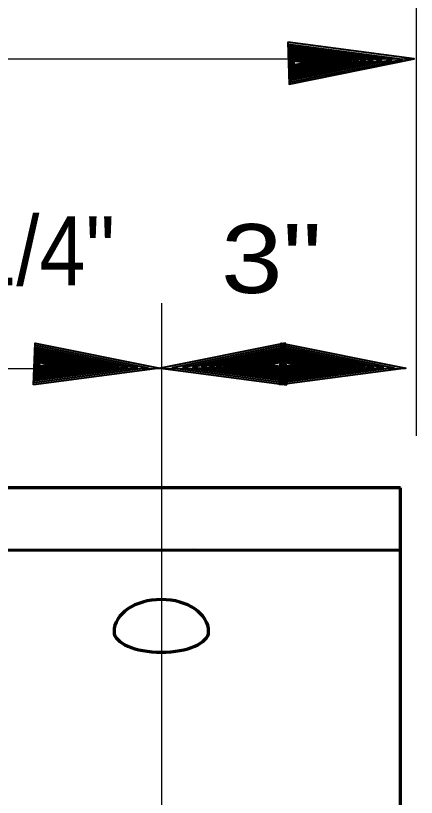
# Model space of a CAD drawing. Extents: x 895.6 to 930.4, y -2278.6 to -2254.7.
# Drawn here: x 918.427 to 919.174, y -2271.618 to -2270.16 of the extents above; entities that cross this region are included whole.
import ezdxf

# ---------------------------------------------------------------- set-up
doc = ezdxf.new("R2010")
doc.units = 0
doc.header["$LTSCALE"] = 0.051
doc.layers.add('1', color=7, linetype='Continuous', lineweight=70)
doc.layers.add('3', color=7, linetype='Continuous', lineweight=40)

msp = doc.modelspace()

# ---------------------------------------------------------------- hatches: boundary and pattern name
at = {"layer": '3'}
for points in [[(918.93467, -2270.20958), (918.93733, -2270.28758), (919.16992, -2270.24067), (919.16992, -2270.24067)], [(918.93583, -2270.2135), (918.93825, -2270.28367), (919.14758, -2270.2415), (919.14758, -2270.2415)], [(918.93692, -2270.217), (918.93908, -2270.28017), (919.1275, -2270.24208), (919.1275, -2270.24208)], [(918.93783, -2270.22008), (918.93983, -2270.27683), (919.10942, -2270.24267), (919.10942, -2270.24267)], [(918.93867, -2270.22275), (918.94042, -2270.274), (919.09317, -2270.24317), (919.09317, -2270.24317)], [(918.93958, -2270.2255), (918.94108, -2270.27142), (919.0785, -2270.24375), (919.0785, -2270.24375)], [(918.94025, -2270.22775), (918.94158, -2270.26917), (919.06533, -2270.24417), (919.06533, -2270.24417)], [(918.941, -2270.22967), (918.94208, -2270.267), (919.05333, -2270.2445), (919.05333, -2270.2445)], [(918.94133, -2270.23158), (918.94258, -2270.26525), (919.04275, -2270.24508), (919.04275, -2270.24508)], [(918.942, -2270.23325), (918.94308, -2270.26358), (919.033, -2270.24525), (919.033, -2270.24525)], [(918.9425, -2270.23475), (918.94333, -2270.26192), (919.02433, -2270.24558), (919.02433, -2270.24558)], [(918.94283, -2270.23617), (918.94375, -2270.26058), (919.01667, -2270.24592), (919.01667, -2270.24592)], [(918.94325, -2270.23725), (918.944, -2270.25933), (919.0095, -2270.24608), (919.0095, -2270.24608)], [(918.94375, -2270.23842), (918.94417, -2270.25825), (919.00333, -2270.24633), (919.00333, -2270.24633)], [(918.94392, -2270.23933), (918.94458, -2270.25725), (918.99767, -2270.24642), (918.99767, -2270.24642)], [(918.94425, -2270.24033), (918.94467, -2270.25642), (918.99258, -2270.24675), (918.99258, -2270.24675)], [(918.9445, -2270.24108), (918.94492, -2270.25567), (918.988, -2270.24692), (918.988, -2270.24692)], [(918.94458, -2270.24183), (918.94508, -2270.25483), (918.98383, -2270.24708), (918.98383, -2270.24708)], [(918.94492, -2270.24225), (918.94525, -2270.25408), (918.98025, -2270.24708), (918.98025, -2270.24708)], [(918.94517, -2270.24283), (918.9455, -2270.25342), (918.977, -2270.24708), (918.977, -2270.24708)], [(918.94542, -2270.24317), (918.94575, -2270.25275), (918.974, -2270.247), (918.974, -2270.247)], [(918.94542, -2270.24375), (918.94575, -2270.25225), (918.97117, -2270.24708), (918.97117, -2270.24708)], [(918.94558, -2270.24425), (918.94592, -2270.25183), (918.96883, -2270.24733), (918.96883, -2270.24733)], [(918.94575, -2270.2445), (918.94592, -2270.25133), (918.96658, -2270.24725), (918.96658, -2270.24725)], [(918.46067, -2270.84892), (918.46333, -2270.77092), (918.696, -2270.81783), (918.696, -2270.81783)], [(918.46192, -2270.845), (918.46425, -2270.77483), (918.67358, -2270.817), (918.67358, -2270.817)], [(918.46292, -2270.8415), (918.46508, -2270.77842), (918.6535, -2270.81642), (918.6535, -2270.81642)], [(918.9325, -2270.84892), (918.92983, -2270.77092), (918.69717, -2270.81783), (918.69717, -2270.81783)], [(918.93125, -2270.845), (918.92892, -2270.77483), (918.71958, -2270.817), (918.71958, -2270.817)], [(918.93025, -2270.8415), (918.92808, -2270.77842), (918.73967, -2270.81642), (918.73967, -2270.81642)], [(918.91925, -2270.849), (918.92192, -2270.771), (919.1545, -2270.81792), (919.1545, -2270.81792)], [(918.92042, -2270.84508), (918.92283, -2270.77492), (919.13217, -2270.81708), (919.13217, -2270.81708)], [(918.9215, -2270.84158), (918.92367, -2270.77842), (919.11208, -2270.8165), (919.11208, -2270.8165)], [(918.46392, -2270.83842), (918.46583, -2270.78167), (918.63542, -2270.81583), (918.63542, -2270.81583)], [(918.46467, -2270.83575), (918.4665, -2270.78458), (918.61917, -2270.81533), (918.61917, -2270.81533)], [(918.46567, -2270.83308), (918.46717, -2270.78708), (918.6045, -2270.81483), (918.6045, -2270.81483)], [(918.46625, -2270.83075), (918.46758, -2270.78933), (918.59133, -2270.81433), (918.59133, -2270.81433)], [(918.467, -2270.82883), (918.46808, -2270.7915), (918.57933, -2270.814), (918.57933, -2270.814)], [(918.92925, -2270.83842), (918.92733, -2270.78167), (918.75775, -2270.81583), (918.75775, -2270.81583)], [(918.9285, -2270.83575), (918.92667, -2270.78458), (918.774, -2270.81533), (918.774, -2270.81533)], [(918.9275, -2270.83308), (918.926, -2270.78708), (918.78867, -2270.81483), (918.78867, -2270.81483)], [(918.92692, -2270.83075), (918.92558, -2270.78933), (918.80183, -2270.81433), (918.80183, -2270.81433)], [(918.92617, -2270.82883), (918.92508, -2270.7915), (918.81383, -2270.814), (918.81383, -2270.814)], [(918.92242, -2270.8385), (918.92442, -2270.78175), (919.094, -2270.81592), (919.094, -2270.81592)], [(918.92325, -2270.83583), (918.925, -2270.78458), (919.07775, -2270.81542), (919.07775, -2270.81542)], [(918.92417, -2270.83308), (918.92567, -2270.78717), (919.06308, -2270.81483), (919.06308, -2270.81483)], [(918.92483, -2270.83083), (918.92617, -2270.78942), (919.04992, -2270.81442), (919.04992, -2270.81442)], [(918.92558, -2270.82892), (918.92667, -2270.79158), (919.03792, -2270.81408), (919.03792, -2270.81408)], [(918.46733, -2270.827), (918.46867, -2270.79333), (918.56875, -2270.8135), (918.56875, -2270.8135)], [(918.468, -2270.82525), (918.46908, -2270.79492), (918.55908, -2270.81325), (918.55908, -2270.81325)], [(918.4685, -2270.82375), (918.46942, -2270.79658), (918.55042, -2270.81292), (918.55042, -2270.81292)], [(918.46883, -2270.82233), (918.46975, -2270.798), (918.54267, -2270.81258), (918.54267, -2270.81258)], [(918.46933, -2270.82125), (918.47, -2270.79917), (918.5355, -2270.81242), (918.5355, -2270.81242)], [(918.46975, -2270.82008), (918.47025, -2270.80025), (918.52942, -2270.81225), (918.52942, -2270.81225)], [(918.47, -2270.81917), (918.47058, -2270.80125), (918.52367, -2270.81208), (918.52367, -2270.81208)], [(918.47025, -2270.81825), (918.47067, -2270.80208), (918.51858, -2270.81175), (918.51858, -2270.81175)], [(918.4705, -2270.81742), (918.471, -2270.80283), (918.514, -2270.81158), (918.514, -2270.81158)], [(918.47067, -2270.81667), (918.47108, -2270.80367), (918.50992, -2270.8115), (918.50992, -2270.8115)], [(918.471, -2270.81625), (918.47125, -2270.80442), (918.50625, -2270.8115), (918.50625, -2270.8115)], [(918.47117, -2270.81567), (918.4715, -2270.80508), (918.503, -2270.81142), (918.503, -2270.81142)], [(918.47142, -2270.81533), (918.47175, -2270.80575), (918.5, -2270.81158), (918.5, -2270.81158)], [(918.47142, -2270.81475), (918.47175, -2270.80625), (918.49725, -2270.81142), (918.49725, -2270.81142)], [(918.47158, -2270.81425), (918.47192, -2270.80667), (918.49483, -2270.81117), (918.49483, -2270.81117)], [(918.47175, -2270.814), (918.472, -2270.80717), (918.49267, -2270.81125), (918.49267, -2270.81125)], [(918.92583, -2270.827), (918.9245, -2270.79333), (918.82442, -2270.8135), (918.82442, -2270.8135)], [(918.92517, -2270.82525), (918.92408, -2270.79492), (918.83408, -2270.81325), (918.83408, -2270.81325)], [(918.92467, -2270.82375), (918.92375, -2270.79658), (918.84275, -2270.81292), (918.84275, -2270.81292)], [(918.92433, -2270.82233), (918.92342, -2270.798), (918.8505, -2270.81258), (918.8505, -2270.81258)], [(918.92383, -2270.82125), (918.92317, -2270.79917), (918.85767, -2270.81242), (918.85767, -2270.81242)], [(918.92342, -2270.82008), (918.92292, -2270.80025), (918.86375, -2270.81225), (918.86375, -2270.81225)], [(918.92317, -2270.81917), (918.92258, -2270.80125), (918.8695, -2270.81208), (918.8695, -2270.81208)], [(918.92292, -2270.81825), (918.9225, -2270.80208), (918.87458, -2270.81175), (918.87458, -2270.81175)], [(918.92267, -2270.81742), (918.92217, -2270.80283), (918.87917, -2270.81158), (918.87917, -2270.81158)], [(918.9225, -2270.81667), (918.92208, -2270.80367), (918.88325, -2270.8115), (918.88325, -2270.8115)], [(918.92217, -2270.81625), (918.92192, -2270.80442), (918.88692, -2270.8115), (918.88692, -2270.8115)], [(918.922, -2270.81567), (918.92167, -2270.80508), (918.89017, -2270.81142), (918.89017, -2270.81142)], [(918.92175, -2270.81533), (918.92142, -2270.80575), (918.89317, -2270.81158), (918.89317, -2270.81158)], [(918.92175, -2270.81475), (918.92142, -2270.80625), (918.89592, -2270.81142), (918.89592, -2270.81142)], [(918.92158, -2270.81425), (918.92125, -2270.80667), (918.89833, -2270.81117), (918.89833, -2270.81117)], [(918.92142, -2270.814), (918.92117, -2270.80717), (918.9005, -2270.81125), (918.9005, -2270.81125)], [(918.92592, -2270.827), (918.92717, -2270.79333), (919.02733, -2270.8135), (919.02733, -2270.8135)], [(918.92658, -2270.82533), (918.92767, -2270.795), (919.01758, -2270.81333), (919.01758, -2270.81333)], [(918.92708, -2270.82383), (918.92792, -2270.79667), (919.00892, -2270.813), (919.00892, -2270.813)], [(918.92742, -2270.82242), (918.92833, -2270.798), (919.00125, -2270.81267), (919.00125, -2270.81267)], [(918.92783, -2270.82133), (918.92858, -2270.79925), (918.99408, -2270.8125), (918.99408, -2270.8125)], [(918.92833, -2270.82017), (918.92875, -2270.80033), (918.98792, -2270.81225), (918.98792, -2270.81225)], [(918.9285, -2270.81925), (918.92917, -2270.80133), (918.98225, -2270.81217), (918.98225, -2270.81217)], [(918.92883, -2270.81825), (918.92925, -2270.80217), (918.97717, -2270.81183), (918.97717, -2270.81183)], [(918.92908, -2270.8175), (918.9295, -2270.80292), (918.97258, -2270.81167), (918.97258, -2270.81167)], [(918.92917, -2270.81675), (918.92967, -2270.80375), (918.96842, -2270.8115), (918.96842, -2270.8115)], [(918.9295, -2270.81633), (918.92983, -2270.8045), (918.96483, -2270.8115), (918.96483, -2270.8115)], [(918.92975, -2270.81575), (918.93008, -2270.80517), (918.96158, -2270.8115), (918.96158, -2270.8115)], [(918.93, -2270.81542), (918.93033, -2270.80583), (918.95858, -2270.81158), (918.95858, -2270.81158)], [(918.93, -2270.81483), (918.93033, -2270.80633), (918.95575, -2270.8115), (918.95575, -2270.8115)], [(918.93017, -2270.81433), (918.9305, -2270.80675), (918.95342, -2270.81125), (918.95342, -2270.81125)], [(918.93033, -2270.81408), (918.9305, -2270.80725), (918.95117, -2270.81133), (918.95117, -2270.81133)]]:
    msp.add_hatch(color=256, dxfattribs=at).paths.add_polyline_path(points)

# ---------------------------------------------------------------- linework, layer by layer
at = {"layer": '1', "lineweight": 25}
for p, q in [((919.17408, -2270.94408), (919.17408, -2269.46433)), ((918.1585, -2270.24067), (919.16992, -2270.24067)), ((918.69942, -2273.34217), (918.69942, -2270.69617)), ((917.64958, -2270.81817), (919.1535, -2270.81817))]:
    msp.add_line(p, q, dxfattribs=at)
at = {"layer": '1'}
for p, q in [((919.14467, -2271.04083), (915.53433, -2271.04083)), ((919.14467, -2273.83717), (919.14467, -2271.04083))]:
    msp.add_line(p, q, dxfattribs=at)
msp.add_lwpolyline([(919.14442, -2271.15792), (918.759, -2271.157), (918.012, -2271.15792), (917.23617, -2271.16342), (917.23658, -2271.1625)], dxfattribs=at)
for major_axis, ratio in [((-0.08819, 0), 0.679978), ((0.08819, 0), 0.434256)]:
    msp.add_ellipse((918.69876, -2271.30925), major_axis=major_axis, ratio=ratio, start_param=3.1415927, end_param=6.2831853, dxfattribs=at)
at = {"layer": '3'}
for points in [[(918.93467, -2270.20958), (918.93733, -2270.28758), (919.16992, -2270.24067), (919.16992, -2270.24067)], [(918.93583, -2270.2135), (918.93825, -2270.28367), (919.14758, -2270.2415), (919.14758, -2270.2415)], [(918.93692, -2270.217), (918.93908, -2270.28017), (919.1275, -2270.24208), (919.1275, -2270.24208)], [(918.93783, -2270.22008), (918.93983, -2270.27683), (919.10942, -2270.24267), (919.10942, -2270.24267)], [(918.93867, -2270.22275), (918.94042, -2270.274), (919.09317, -2270.24317), (919.09317, -2270.24317)], [(918.93958, -2270.2255), (918.94108, -2270.27142), (919.0785, -2270.24375), (919.0785, -2270.24375)], [(918.94025, -2270.22775), (918.94158, -2270.26917), (919.06533, -2270.24417), (919.06533, -2270.24417)], [(918.941, -2270.22967), (918.94208, -2270.267), (919.05333, -2270.2445), (919.05333, -2270.2445)], [(918.94133, -2270.23158), (918.94258, -2270.26525), (919.04275, -2270.24508), (919.04275, -2270.24508)], [(918.942, -2270.23325), (918.94308, -2270.26358), (919.033, -2270.24525), (919.033, -2270.24525)], [(918.9425, -2270.23475), (918.94333, -2270.26192), (919.02433, -2270.24558), (919.02433, -2270.24558)], [(918.94283, -2270.23617), (918.94375, -2270.26058), (919.01667, -2270.24592), (919.01667, -2270.24592)], [(918.94325, -2270.23725), (918.944, -2270.25933), (919.0095, -2270.24608), (919.0095, -2270.24608)], [(918.94375, -2270.23842), (918.94417, -2270.25825), (919.00333, -2270.24633), (919.00333, -2270.24633)], [(918.94392, -2270.23933), (918.94458, -2270.25725), (918.99767, -2270.24642), (918.99767, -2270.24642)], [(918.94425, -2270.24033), (918.94467, -2270.25642), (918.99258, -2270.24675), (918.99258, -2270.24675)], [(918.9445, -2270.24108), (918.94492, -2270.25567), (918.988, -2270.24692), (918.988, -2270.24692)], [(918.94458, -2270.24183), (918.94508, -2270.25483), (918.98383, -2270.24708), (918.98383, -2270.24708)], [(918.94492, -2270.24225), (918.94525, -2270.25408), (918.98025, -2270.24708), (918.98025, -2270.24708)], [(918.94517, -2270.24283), (918.9455, -2270.25342), (918.977, -2270.24708), (918.977, -2270.24708)], [(918.94542, -2270.24317), (918.94575, -2270.25275), (918.974, -2270.247), (918.974, -2270.247)], [(918.94542, -2270.24375), (918.94575, -2270.25225), (918.97117, -2270.24708), (918.97117, -2270.24708)], [(918.94558, -2270.24425), (918.94592, -2270.25183), (918.96883, -2270.24733), (918.96883, -2270.24733)], [(918.94575, -2270.2445), (918.94592, -2270.25133), (918.96658, -2270.24725), (918.96658, -2270.24725)], [(918.46067, -2270.84892), (918.46333, -2270.77092), (918.696, -2270.81783), (918.696, -2270.81783)], [(918.46192, -2270.845), (918.46425, -2270.77483), (918.67358, -2270.817), (918.67358, -2270.817)], [(918.46292, -2270.8415), (918.46508, -2270.77842), (918.6535, -2270.81642), (918.6535, -2270.81642)], [(918.9325, -2270.84892), (918.92983, -2270.77092), (918.69717, -2270.81783), (918.69717, -2270.81783)], [(918.93125, -2270.845), (918.92892, -2270.77483), (918.71958, -2270.817), (918.71958, -2270.817)], [(918.93025, -2270.8415), (918.92808, -2270.77842), (918.73967, -2270.81642), (918.73967, -2270.81642)], [(918.91925, -2270.849), (918.92192, -2270.771), (919.1545, -2270.81792), (919.1545, -2270.81792)], [(918.92042, -2270.84508), (918.92283, -2270.77492), (919.13217, -2270.81708), (919.13217, -2270.81708)], [(918.9215, -2270.84158), (918.92367, -2270.77842), (919.11208, -2270.8165), (919.11208, -2270.8165)], [(918.46392, -2270.83842), (918.46583, -2270.78167), (918.63542, -2270.81583), (918.63542, -2270.81583)], [(918.46467, -2270.83575), (918.4665, -2270.78458), (918.61917, -2270.81533), (918.61917, -2270.81533)], [(918.46567, -2270.83308), (918.46717, -2270.78708), (918.6045, -2270.81483), (918.6045, -2270.81483)], [(918.46625, -2270.83075), (918.46758, -2270.78933), (918.59133, -2270.81433), (918.59133, -2270.81433)], [(918.467, -2270.82883), (918.46808, -2270.7915), (918.57933, -2270.814), (918.57933, -2270.814)], [(918.92925, -2270.83842), (918.92733, -2270.78167), (918.75775, -2270.81583), (918.75775, -2270.81583)], [(918.9285, -2270.83575), (918.92667, -2270.78458), (918.774, -2270.81533), (918.774, -2270.81533)], [(918.9275, -2270.83308), (918.926, -2270.78708), (918.78867, -2270.81483), (918.78867, -2270.81483)], [(918.92692, -2270.83075), (918.92558, -2270.78933), (918.80183, -2270.81433), (918.80183, -2270.81433)], [(918.92617, -2270.82883), (918.92508, -2270.7915), (918.81383, -2270.814), (918.81383, -2270.814)], [(918.92242, -2270.8385), (918.92442, -2270.78175), (919.094, -2270.81592), (919.094, -2270.81592)], [(918.92325, -2270.83583), (918.925, -2270.78458), (919.07775, -2270.81542), (919.07775, -2270.81542)], [(918.92417, -2270.83308), (918.92567, -2270.78717), (919.06308, -2270.81483), (919.06308, -2270.81483)], [(918.92483, -2270.83083), (918.92617, -2270.78942), (919.04992, -2270.81442), (919.04992, -2270.81442)], [(918.92558, -2270.82892), (918.92667, -2270.79158), (919.03792, -2270.81408), (919.03792, -2270.81408)], [(918.46733, -2270.827), (918.46867, -2270.79333), (918.56875, -2270.8135), (918.56875, -2270.8135)], [(918.468, -2270.82525), (918.46908, -2270.79492), (918.55908, -2270.81325), (918.55908, -2270.81325)], [(918.4685, -2270.82375), (918.46942, -2270.79658), (918.55042, -2270.81292), (918.55042, -2270.81292)], [(918.46883, -2270.82233), (918.46975, -2270.798), (918.54267, -2270.81258), (918.54267, -2270.81258)], [(918.46933, -2270.82125), (918.47, -2270.79917), (918.5355, -2270.81242), (918.5355, -2270.81242)], [(918.46975, -2270.82008), (918.47025, -2270.80025), (918.52942, -2270.81225), (918.52942, -2270.81225)], [(918.47, -2270.81917), (918.47058, -2270.80125), (918.52367, -2270.81208), (918.52367, -2270.81208)], [(918.47025, -2270.81825), (918.47067, -2270.80208), (918.51858, -2270.81175), (918.51858, -2270.81175)], [(918.4705, -2270.81742), (918.471, -2270.80283), (918.514, -2270.81158), (918.514, -2270.81158)], [(918.47067, -2270.81667), (918.47108, -2270.80367), (918.50992, -2270.8115), (918.50992, -2270.8115)], [(918.471, -2270.81625), (918.47125, -2270.80442), (918.50625, -2270.8115), (918.50625, -2270.8115)], [(918.47117, -2270.81567), (918.4715, -2270.80508), (918.503, -2270.81142), (918.503, -2270.81142)], [(918.47142, -2270.81533), (918.47175, -2270.80575), (918.5, -2270.81158), (918.5, -2270.81158)], [(918.47142, -2270.81475), (918.47175, -2270.80625), (918.49725, -2270.81142), (918.49725, -2270.81142)], [(918.47158, -2270.81425), (918.47192, -2270.80667), (918.49483, -2270.81117), (918.49483, -2270.81117)], [(918.47175, -2270.814), (918.472, -2270.80717), (918.49267, -2270.81125), (918.49267, -2270.81125)], [(918.92583, -2270.827), (918.9245, -2270.79333), (918.82442, -2270.8135), (918.82442, -2270.8135)], [(918.92517, -2270.82525), (918.92408, -2270.79492), (918.83408, -2270.81325), (918.83408, -2270.81325)], [(918.92467, -2270.82375), (918.92375, -2270.79658), (918.84275, -2270.81292), (918.84275, -2270.81292)], [(918.92433, -2270.82233), (918.92342, -2270.798), (918.8505, -2270.81258), (918.8505, -2270.81258)], [(918.92383, -2270.82125), (918.92317, -2270.79917), (918.85767, -2270.81242), (918.85767, -2270.81242)], [(918.92342, -2270.82008), (918.92292, -2270.80025), (918.86375, -2270.81225), (918.86375, -2270.81225)], [(918.92317, -2270.81917), (918.92258, -2270.80125), (918.8695, -2270.81208), (918.8695, -2270.81208)], [(918.92292, -2270.81825), (918.9225, -2270.80208), (918.87458, -2270.81175), (918.87458, -2270.81175)], [(918.92267, -2270.81742), (918.92217, -2270.80283), (918.87917, -2270.81158), (918.87917, -2270.81158)], [(918.9225, -2270.81667), (918.92208, -2270.80367), (918.88325, -2270.8115), (918.88325, -2270.8115)], [(918.92217, -2270.81625), (918.92192, -2270.80442), (918.88692, -2270.8115), (918.88692, -2270.8115)], [(918.922, -2270.81567), (918.92167, -2270.80508), (918.89017, -2270.81142), (918.89017, -2270.81142)], [(918.92175, -2270.81533), (918.92142, -2270.80575), (918.89317, -2270.81158), (918.89317, -2270.81158)], [(918.92175, -2270.81475), (918.92142, -2270.80625), (918.89592, -2270.81142), (918.89592, -2270.81142)], [(918.92158, -2270.81425), (918.92125, -2270.80667), (918.89833, -2270.81117), (918.89833, -2270.81117)], [(918.92142, -2270.814), (918.92117, -2270.80717), (918.9005, -2270.81125), (918.9005, -2270.81125)], [(918.92592, -2270.827), (918.92717, -2270.79333), (919.02733, -2270.8135), (919.02733, -2270.8135)], [(918.92658, -2270.82533), (918.92767, -2270.795), (919.01758, -2270.81333), (919.01758, -2270.81333)], [(918.92708, -2270.82383), (918.92792, -2270.79667), (919.00892, -2270.813), (919.00892, -2270.813)], [(918.92742, -2270.82242), (918.92833, -2270.798), (919.00125, -2270.81267), (919.00125, -2270.81267)], [(918.92783, -2270.82133), (918.92858, -2270.79925), (918.99408, -2270.8125), (918.99408, -2270.8125)], [(918.92833, -2270.82017), (918.92875, -2270.80033), (918.98792, -2270.81225), (918.98792, -2270.81225)], [(918.9285, -2270.81925), (918.92917, -2270.80133), (918.98225, -2270.81217), (918.98225, -2270.81217)], [(918.92883, -2270.81825), (918.92925, -2270.80217), (918.97717, -2270.81183), (918.97717, -2270.81183)], [(918.92908, -2270.8175), (918.9295, -2270.80292), (918.97258, -2270.81167), (918.97258, -2270.81167)], [(918.92917, -2270.81675), (918.92967, -2270.80375), (918.96842, -2270.8115), (918.96842, -2270.8115)], [(918.9295, -2270.81633), (918.92983, -2270.8045), (918.96483, -2270.8115), (918.96483, -2270.8115)], [(918.92975, -2270.81575), (918.93008, -2270.80517), (918.96158, -2270.8115), (918.96158, -2270.8115)], [(918.93, -2270.81542), (918.93033, -2270.80583), (918.95858, -2270.81158), (918.95858, -2270.81158)], [(918.93, -2270.81483), (918.93033, -2270.80633), (918.95575, -2270.8115), (918.95575, -2270.8115)], [(918.93017, -2270.81433), (918.9305, -2270.80675), (918.95342, -2270.81125), (918.95342, -2270.81125)], [(918.93033, -2270.81408), (918.9305, -2270.80725), (918.95117, -2270.81133), (918.95117, -2270.81133)]]:
    msp.add_lwpolyline(points, close=True, dxfattribs=at)

# ---------------------------------------------------------------- texts
at = {"layer": '1'}
for s, width, p in [('4 1/4"', 0.9, (918.21333, -2270.66283)), ('3"', 1.2, (918.81, -2270.67742))]:
    msp.add_text(s, height=0.1286, dxfattribs=dict(at, width=width)).set_placement(p)

doc.saveas('drawing.dxf')
